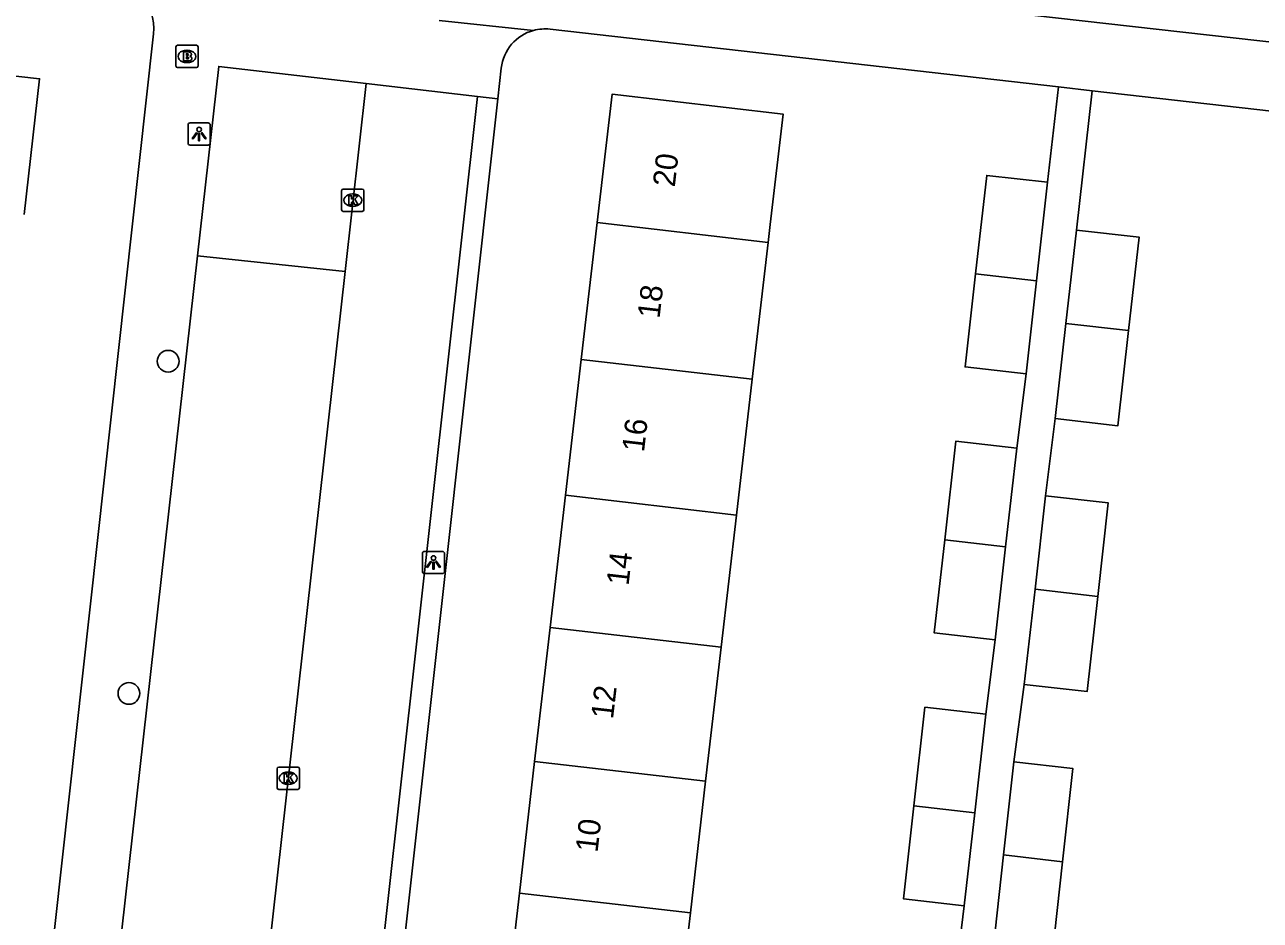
# Model space of a CAD drawing. Extents: x 161928 to 163055, y 386475 to 387428.
# Drawn here: x 162193.1 to 162248.6, y 387352.1 to 387392.4 of the extents above; entities that cross this region are included whole.
import ezdxf

# ---------------------------------------------------------------- set-up
doc = ezdxf.new("R2010")
doc.units = 0
for name, color, linetype in [('IMGEO_Boom', 7, 'Continuous'), ('IMGEO_Brandkraan', 7, 'Continuous'), ('IMGEO_Kolk', 7, 'Continuous'), ('IMGEO_Lichtpunt', 7, 'Continuous'), ('IMGEO_Pand', 7, 'Continuous'), ('IMGEO_Pand_nummerreeks', 7, 'Continuous'), ('IMGEO_Parkeervlak_open', 7, 'Continuous'), ('IMGEO_Rijbaan_lokaal_open', 7, 'Continuous'), ('IMGEO_Voetpad_open', 7, 'Continuous')]:
    doc.layers.add(name, color=color, linetype=linetype)

msp = doc.modelspace()

# ---------------------------------------------------------------- linework, layer by layer
at = {"layer": 'IMGEO_Boom'}
for centre in [(162199.513, 387377.232), (162197.751, 387362.308)]:
    msp.add_circle(centre, 0.489, dxfattribs=at)
at = {"layer": 'IMGEO_Brandkraan'}
for p, q in [((162199.932, 387391.432), (162200.784, 387391.432)), ((162199.857, 387390.506), (162199.857, 387391.358)), ((162200.345, 387391.212), (162200.37, 387391.212)), ((162200.858, 387391.358), (162200.858, 387390.506)), ((162200.784, 387390.432), (162199.932, 387390.432)), ((162200.368, 387390.652), (162200.343, 387390.652))]:
    msp.add_line(p, q, dxfattribs=at)
for points in [[(162199.932, 387391.432), (162200.784, 387391.432)], [(162199.857, 387390.506), (162199.857, 387391.358)], [(162200.205, 387391.132), (162200.205, 387390.732), (162200.418, 387390.732)], [(162200.436, 387391.132), (162200.205, 387391.132)], [(162200.384, 387391.051), (162200.33, 387391.051), (162200.33, 387390.975)], [(162200.33, 387390.975), (162200.383, 387390.975)], [(162200.392, 387390.899), (162200.33, 387390.899), (162200.33, 387390.818)], [(162200.33, 387390.818), (162200.392, 387390.818)], [(162200.858, 387391.358), (162200.858, 387390.506)], [(162200.784, 387390.432), (162199.932, 387390.432)]]:
    msp.add_lwpolyline(points, dxfattribs=at)
for centre, radius, start, end in [((162199.934, 387391.356), 0.0765, 91.552, 178.448), ((162199.934, 387391.356), 0.0765, 91.552, 178.448), ((162200.782, 387391.356), 0.0765, 1.552, 88.448), ((162200.782, 387391.356), 0.0765, 1.552, 88.448), ((162200.385, 387391.013), 0.0379, 267.8285, 90.9355), ((162200.393, 387390.858), 0.0404, 269.8759, 90.5077), ((162200.44, 387390.987), 0.145, 59.4692, 91.5367), ((162200.465, 387391.034), 0.0922, 285.5137, 58.1501), ((162200.47, 387390.842), 0.105, 301.3115, 78.989), ((162199.934, 387390.508), 0.0765, 181.552, 268.448), ((162199.934, 387390.508), 0.0765, 181.552, 268.448), ((162200.424, 387390.983), 0.251, 268.6676, 293.5347), ((162200.782, 387390.508), 0.0765, 271.552, 358.448), ((162200.782, 387390.508), 0.0765, 271.552, 358.448)]:
    msp.add_arc(centre, radius, start, end, dxfattribs=at)
for centre, major_axis, ratio, start_param, end_param in [((162200.344, 387390.932), (-0.387, 0.002), 0.722429, 4.712389, 7.853982), ((162200.369, 387390.932), (-0.39, 0.002), 0.717154, 1.570796, 4.712389)]:
    msp.add_ellipse(centre, major_axis=major_axis, ratio=ratio, start_param=start_param, end_param=end_param, dxfattribs=at)
at = {"layer": 'IMGEO_Kolk'}
for p, q in [((162207.305, 387384.044), (162207.305, 387384.896)), ((162207.38, 387384.97), (162208.232, 387384.97)), ((162207.793, 387384.75), (162207.818, 387384.75)), ((162208.306, 387384.896), (162208.306, 387384.044)), ((162207.816, 387384.19), (162207.791, 387384.19)), ((162208.232, 387383.97), (162207.38, 387383.97)), ((162204.404, 387358.069), (162204.404, 387358.921)), ((162204.479, 387358.995), (162205.331, 387358.995)), ((162204.892, 387358.775), (162204.917, 387358.775)), ((162205.405, 387358.921), (162205.405, 387358.069)), ((162204.915, 387358.215), (162204.89, 387358.215)), ((162205.331, 387357.995), (162204.479, 387357.995))]:
    msp.add_line(p, q, dxfattribs=at)
for points in [[(162207.305, 387384.044), (162207.305, 387384.896)], [(162207.38, 387384.97), (162208.232, 387384.97)], [(162208.306, 387384.896), (162208.306, 387384.044)], [(162207.626, 387384.67), (162207.749, 387384.67), (162207.749, 387384.519), (162207.879, 387384.67), (162208.043, 387384.67), (162207.897, 387384.519), (162208.05, 387384.27), (162207.898, 387384.27), (162207.813, 387384.434), (162207.749, 387384.367), (162207.749, 387384.27), (162207.626, 387384.27), (162207.626, 387384.67)], [(162208.232, 387383.97), (162207.38, 387383.97)], [(162204.404, 387358.069), (162204.404, 387358.921)], [(162204.479, 387358.995), (162205.331, 387358.995)], [(162204.725, 387358.695), (162204.848, 387358.695), (162204.848, 387358.544), (162204.978, 387358.695), (162205.142, 387358.695), (162204.996, 387358.544), (162205.149, 387358.295), (162204.997, 387358.295), (162204.912, 387358.459), (162204.848, 387358.392), (162204.848, 387358.295), (162204.725, 387358.295), (162204.725, 387358.695)], [(162205.405, 387358.921), (162205.405, 387358.069)], [(162205.331, 387357.995), (162204.479, 387357.995)]]:
    msp.add_lwpolyline(points, dxfattribs=at)
for centre, start, end in [((162207.382, 387384.894), 91.552, 178.448), ((162207.382, 387384.894), 91.552, 178.448), ((162208.23, 387384.894), 1.552, 88.448), ((162208.23, 387384.894), 1.552, 88.448), ((162207.382, 387384.046), 181.552, 268.448), ((162207.382, 387384.046), 181.552, 268.448), ((162208.23, 387384.046), 271.552, 358.448), ((162208.23, 387384.046), 271.552, 358.448), ((162204.481, 387358.919), 91.552, 178.448), ((162204.481, 387358.919), 91.552, 178.448), ((162205.329, 387358.919), 1.552, 88.448), ((162205.329, 387358.919), 1.552, 88.448), ((162204.481, 387358.071), 181.552, 268.448), ((162204.481, 387358.071), 181.552, 268.448), ((162205.329, 387358.071), 271.552, 358.448), ((162205.329, 387358.071), 271.552, 358.448)]:
    msp.add_arc(centre, 0.0765, start, end, dxfattribs=at)
for centre, major_axis, ratio, start_param, end_param in [((162207.792, 387384.47), (-0.387, 0.002), 0.722429, 4.712389, 7.853982), ((162207.817, 387384.47), (-0.39, 0.002), 0.717154, 1.570796, 4.712389), ((162204.891, 387358.495), (-0.387, 0.002), 0.722429, 4.712389, 7.853982), ((162204.916, 387358.495), (-0.39, 0.002), 0.717154, 1.570796, 4.712389)]:
    msp.add_ellipse(centre, major_axis=major_axis, ratio=ratio, start_param=start_param, end_param=end_param, dxfattribs=at)
at = {"layer": 'IMGEO_Lichtpunt'}
for p, q in [((162200.404, 387387.85), (162200.404, 387387.043)), ((162200.404, 387387.85), (162200.404, 387387.043)), ((162201.306, 387387.945), (162200.498, 387387.945)), ((162201.306, 387387.945), (162200.498, 387387.945)), ((162201.4, 387387.043), (162201.4, 387387.85)), ((162201.4, 387387.043), (162201.4, 387387.85)), ((162200.498, 387386.949), (162201.306, 387386.949)), ((162200.498, 387386.949), (162201.306, 387386.949)), ((162211.835, 387368.688), (162211.027, 387368.688)), ((162211.835, 387368.688), (162211.027, 387368.688)), ((162210.933, 387368.593), (162210.933, 387367.786)), ((162210.933, 387368.593), (162210.933, 387367.786)), ((162211.929, 387367.786), (162211.929, 387368.593)), ((162211.929, 387367.786), (162211.929, 387368.593)), ((162211.027, 387367.692), (162211.835, 387367.692)), ((162211.027, 387367.692), (162211.835, 387367.692))]:
    msp.add_line(p, q, dxfattribs=at)
for points in [[(162200.778, 387387.514), (162200.817, 387387.486), (162200.629, 387387.224), (162200.591, 387387.251), (162200.778, 387387.514)], [(162200.99, 387387.486), (162201.028, 387387.513), (162201.215, 387387.251), (162201.176, 387387.223), (162200.99, 387387.486)], [(162200.88, 387387.466), (162200.927, 387387.466), (162200.927, 387387.144), (162200.88, 387387.144), (162200.88, 387387.466)], [(162211.307, 387368.257), (162211.346, 387368.229), (162211.158, 387367.967), (162211.12, 387367.994), (162211.307, 387368.257)], [(162211.409, 387368.209), (162211.456, 387368.209), (162211.456, 387367.887), (162211.409, 387367.887), (162211.409, 387368.209)], [(162211.519, 387368.229), (162211.557, 387368.256), (162211.744, 387367.994), (162211.705, 387367.966), (162211.519, 387368.229)]]:
    msp.add_lwpolyline(points, dxfattribs=at)
for centre in [(162200.903, 387387.648), (162211.432, 387368.391)]:
    msp.add_circle(centre, 0.0994, dxfattribs=at)
for centre, start, end in [((162200.498, 387387.85), 90, 180), ((162200.498, 387387.85), 90, 180), ((162201.306, 387387.85), 0, 90), ((162201.306, 387387.85), 0, 90), ((162200.498, 387387.043), 180, 270), ((162200.498, 387387.043), 180, 270), ((162201.306, 387387.043), 270, 0), ((162201.306, 387387.043), 270, 360), ((162211.027, 387368.593), 90, 180), ((162211.027, 387368.593), 90, 180), ((162211.835, 387368.593), 0, 90), ((162211.835, 387368.593), 0, 90), ((162211.027, 387367.786), 180, 270), ((162211.027, 387367.786), 180, 270), ((162211.835, 387367.786), 270, 0), ((162211.835, 387367.786), 270, 360)]:
    msp.add_arc(centre, 0.0946, start, end, dxfattribs=at)
at = {"layer": 'IMGEO_Pand'}
for points in [[(162193.043, 387383.828), (162193.732, 387389.928), (162186.161, 387390.783), (162185.472, 387384.682)], [(162218.785, 387383.467), (162219.454, 387389.23), (162227.134, 387388.339), (162226.558, 387383.373), (162226.466, 387382.576)], [(162235.785, 387381.16), (162236.284, 387385.586), (162239.021, 387385.278)], [(162239.021, 387385.278), (162238.521, 387380.843)], [(162218.072, 387377.319), (162218.785, 387383.467)], [(162226.466, 387382.576), (162218.785, 387383.467)], [(162239.839, 387378.937), (162240.311, 387383.129)], [(162240.311, 387383.129), (162243.13, 387382.811), (162242.657, 387378.61)], [(162226.466, 387382.576), (162225.752, 387376.428)], [(162238.051, 387376.67), (162235.314, 387376.979), (162235.785, 387381.16)], [(162235.785, 387381.16), (162238.521, 387380.843)], [(162238.521, 387380.843), (162238.051, 387376.67)], [(162239.357, 387374.656), (162239.839, 387378.937)], [(162242.657, 387378.61), (162242.175, 387374.338), (162239.357, 387374.656)], [(162242.657, 387378.61), (162239.839, 387378.937)], [(162217.364, 387371.213), (162218.072, 387377.319)], [(162218.072, 387377.319), (162225.752, 387376.428)], [(162225.752, 387376.428), (162225.044, 387370.322)], [(162234.398, 387369.209), (162234.897, 387373.635), (162237.634, 387373.327)], [(162237.634, 387373.327), (162237.134, 387368.892)], [(162216.674, 387365.268), (162217.364, 387371.213)], [(162225.044, 387370.322), (162217.364, 387371.213)], [(162238.454, 387366.99), (162238.926, 387371.182)], [(162238.926, 387371.182), (162241.745, 387370.864), (162241.272, 387366.664)], [(162225.044, 387370.322), (162224.354, 387364.378)], [(162236.664, 387364.719), (162233.927, 387365.028), (162234.398, 387369.209)], [(162234.398, 387369.209), (162237.134, 387368.892)], [(162237.134, 387368.892), (162236.664, 387364.719)], [(162237.972, 387362.709), (162238.454, 387366.99)], [(162238.454, 387366.99), (162241.272, 387366.664)], [(162241.272, 387366.664), (162240.79, 387362.391), (162237.972, 387362.709)], [(162215.976, 387359.251), (162216.674, 387365.268)], [(162216.674, 387365.268), (162224.354, 387364.378)], [(162224.354, 387364.378), (162223.656, 387358.36)], [(162233.011, 387357.258), (162233.51, 387361.684), (162236.247, 387361.376)], [(162236.247, 387361.376), (162235.747, 387356.941)], [(162215.29, 387353.335), (162215.976, 387359.251)], [(162215.976, 387359.251), (162223.656, 387358.36)], [(162237.038, 387355.048), (162237.496, 387359.237)], [(162237.496, 387359.237), (162240.147, 387358.94), (162239.688, 387354.741)], [(162223.656, 387358.36), (162222.97, 387352.444)], [(162235.277, 387352.768), (162232.54, 387353.077), (162233.011, 387357.258)], [(162233.011, 387357.258), (162235.747, 387356.941)], [(162235.747, 387356.941), (162235.277, 387352.768)], [(162236.712, 387350.641), (162236.557, 387350.658), (162237.038, 387355.048)], [(162239.688, 387354.741), (162239.209, 387350.361), (162236.712, 387350.641)], [(162239.688, 387354.741), (162237.038, 387355.048)], [(162214.585, 387347.263), (162215.29, 387353.335)], [(162222.97, 387352.444), (162215.29, 387353.335)], [(162222.97, 387352.444), (162222.265, 387346.372)]]:
    msp.add_lwpolyline(points, dxfattribs=at)
at = {"layer": 'IMGEO_Parkeervlak_open'}
msp.add_lwpolyline([(162207.457, 387381.271), (162200.826, 387381.966)], dxfattribs=at)
at = {"layer": 'IMGEO_Rijbaan_lokaal_open'}
for points in [[(162208.402, 387389.715), (162207.457, 387381.271)], [(162208.402, 387389.715), (162213.405, 387389.136)], [(162213.405, 387389.136), (162205.872, 387321.481), (162205.225, 387315.67), (162202.319, 387289.572)], [(162202.698, 387338.766), (162207.457, 387381.271)]]:
    msp.add_lwpolyline(points, dxfattribs=at)
at = {"layer": 'IMGEO_Voetpad_open'}
for points in [[(162323.737, 387387.033), (162323.31, 387383.218), (162314.401, 387384.219), (162223.548, 387394.464), (162215.583, 387395.363)], [(162211.686, 387392.546), (162215.927, 387392.1)], [(162190.611, 387317.551), (162198.854, 387391.946)], [(162216.668, 387392.156), (162239.507, 387389.565)], [(162200.826, 387381.966), (162201.782, 387390.481), (162208.402, 387389.715)], [(162214.478, 387390.405), (162214.326, 387389.032)], [(162239.021, 387385.278), (162239.507, 387389.565)], [(162239.507, 387389.565), (162241.022, 387389.393)], [(162241.022, 387389.393), (162240.311, 387383.129)], [(162241.022, 387389.393), (162264.01, 387386.785)], [(162207.766, 387329.907), (162214.326, 387389.032)], [(162214.326, 387389.032), (162213.405, 387389.136)], [(162200.826, 387381.966), (162196.451, 387343.003)], [(162237.634, 387373.327), (162238.051, 387376.67)], [(162239.357, 387374.656), (162238.926, 387371.182)], [(162236.247, 387361.376), (162236.664, 387364.719)], [(162237.972, 387362.709), (162237.496, 387359.237)], [(162234.861, 387349.425), (162235.277, 387352.768)]]:
    msp.add_lwpolyline(points, dxfattribs=at)
for centre, radius, start, end in [((162196.577, 387392.174), 2.289, 354.2889, 43.4937), ((162216.447, 387390.189), 1.981, 105.215, 173.7329), ((162216.444, 387390.184), 1.985, 83.5321, 105.1116)]:
    msp.add_arc(centre, radius, start, end, dxfattribs=at)

# ---------------------------------------------------------------- texts
at = {"layer": 'IMGEO_Pand_nummerreeks'}
for s, p in [('20', (162222.27, 387385.035)), ('18', (162221.584, 387379.127)), ('16', (162220.888, 387373.125)), ('14', (162220.192, 387367.127)), ('12', (162219.495, 387361.125)), ('10', (162218.8, 387355.133))]:
    msp.add_text(s, height=1, rotation=83.3827, dxfattribs=at).set_placement(p)

doc.saveas('drawing.dxf')
